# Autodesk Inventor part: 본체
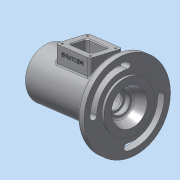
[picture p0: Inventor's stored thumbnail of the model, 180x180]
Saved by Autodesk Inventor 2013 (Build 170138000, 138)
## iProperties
Created: 2017-05
Part Number: 본체
Material: 알루미늄 6061
Document SubType Name: Modeling
Designer: dgall
Density: 2.71 g/cm^3
Mass: 681.559 g
Surface Area: 621.113 cm^2
Volume: 251.498 cm^3
Author: dgall
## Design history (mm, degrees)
sketch "스케치1"
  geometry: L1 (-57.5, 0)-(57.5, 0); L2 (44.5, 53)-(54.5, 53); L3 (57.5, 0)-(57.5, 31); L4 (57.5, 31)-(54.5, 31); L5 (54.5, 31)-(54.5, 53); L6 (44.5, 53)-(44.5, 31); L7 (44.5, 31)-(-57.5, 31); L8 (-57.5, 0)-(-57.5, 31); L9 (43.5, 16)-(57.5, 22); L10 (43.5, 16)-(43.5, 12.5); L11 (43.5, 12.5)-(36.5, 12.5); L12 (36.2, 12.2)-(36.2, 10); L13 (36.2, 10)-(33.5, 10); L14 (33.5, 16.5)-(28.5, 16.5); L15 (33.5, 16.5)-(33.5, 10); L16 (17.5, 26)-(-20.5, 26); L17 (17.5, 26)-(17.5, 17.5); L18 (-20.5, 17.5)-(-31.5, 17.5); L19 (-31.5, 18.5)-(-33.25, 18.5); L20 (-33.25, 17.5)-(-36.5, 17.5); L21 (-20.5, 26)-(-20.5, 17.5); L22 (-31.5, 18.5)-(-31.5, 17.5); L23 (-33.25, 18.5)-(-33.25, 17.5); L24 (-36.5, 20)-(-45.5, 20); L25 (-36.5, 20)-(-36.5, 17.5); L26 (28.5, 17.5)-(17.5, 17.5); L27 (28.5, 17.5)-(28.5, 16.5); L28 (-45.5, 24)-(-48.5, 24); L29 (-45.5, 24)-(-45.5, 20); L30 (-48.5, 24)-(-48.5, 0); A1 r 0.3 centre (36.5, 12.2) between (36.5, 12.5) and (36.2, 12.2); 3 further points
  constraints: 60 end point, 20 perpendicular, 8 parallel, 4 point on line, 2 collinear, 2 point on circle, 2 tangent, 1 centre point, 1 coincident, 1 horizontal, 1 midpoint
  dimensions: "d0" = 115 distance of L1.start L1.end; "d1" = 106 diameter of L2 L1; "d2" = 3 distance of L3.end L4.end; "d3" = 62 diameter of L4 L1; "d4" = 13 distance between parallel lines of L3 L6; "d5" = 14 distance between parallel lines of L3 L10; "d6" = 32 diameter of L9.start L1; "d7" = 44 diameter of L9.end L1; "d8" = 7.3 distance of L10.end point (36.2, 12.5); "d9" = 25 diameter of L11 L1; "d10" = 2.7 distance of L13.end L12.end; "d11" = 20 diameter of L13 L1; "d12" = 0.3 radius of A1; "d13" = 5 distance of L14.end L14.start; "d14" = 33 diameter of L14 L1; "d15" = 38 distance of L16.start L16.end; "d16" = 52 diameter of L16 L1; "d17" = 11 distance of L18.start L18.end; "d18" = 35 diameter of L18 L1; "d19" = 1.75 distance of L19.start L19.end; "d20" = 37 diameter of L19 L1; "d21" = 3.25 distance of L20.start L20.end; "d22" = 9 distance of L24.start L24.end; "d23" = 40 diameter of L24 L1; "d24" = 11 distance of L17.end L26.start; "d25" = 35 diameter of L26 L1; "d26" = 3 distance of L28.start L28.end; "d27" = 48 diameter of L28 L1
revolve "회전1" sketch "스케치1" stored, may be unused: angle "d28" = 90 deg
node "작업 평면1"
sketch "스케치4"
  geometry: L1 (-76.893, 0)-(76.893, 0) reference; L2 (0, -76.893)-(0, 76.893) reference; C1 r 53 at (0, 0) reference; A1 r 4 centre (41.5, 0) between (45.5, 0) and (37.5, 0); A2 r 4 centre (0, -41.5) between (0, -37.5) and (0, -45.5); A3 r 4 centre (0, 41.5) between (0, 37.5) and (0, 45.5); A4 r 4 centre (-41.5, 0) between (-45.5, 0) and (-37.5, 0); A5 r 45.5 centre (0, 0) between (0, 45.5) and (-45.5, 0); A6 r 45.5 centre (0, 0) between (0, -45.5) and (45.5, 0); A7 r 41.5 centre (0, 0) between (3.995, 41.307) and (-41.307, -3.995); A8 r 41.5 centre (0, 0) between (-3.995, -41.307) and (41.307, 3.995); A9 r 37.5 centre (0, 0) between (0, 37.5) and (-37.5, 0); A10 r 37.5 centre (0, 0) between (0, -37.5) and (37.5, 0)
  constraints: 28 point on circle, 10 centre point, 5 equal radius, 5 point on line, 1 coincident
  dimensions: "d43" = 8 diameter of A1; "d46" = 45.5 radius of A6; "d47" = 41.5 radius of A8; "d48" = 37.5 radius of A10
extrude "돌출3" cut sketch "스케치4" stored distance "d49" = 10; taper "d50" = 0 deg
sketch "스케치5"
  geometry: L1 (26.5, -20)-(-23.5, -20); L2 (-23.5, -20)-(-23.5, 20); L3 (-23.5, 20)-(26.5, 20); L4 (26.5, 20)-(26.5, -20); L5 (57.5, 31)-(57.5, -31) reference; L6 (-80.5, 0)-(80.5, 0) reference; 1 further point
  constraints: 8 end point, 2 parallel, 1 horizontal, 1 perpendicular, 1 other
  dimensions: "d56" = 31 distance between parallel lines of L5 L4; "d57" = 50 distance between parallel lines of L2 L4; "d58" = 40 distance between parallel lines of L3 L1
extrude "돌출4" join sketch "스케치5" stored distance "d59" = 10; taper "d60" = 0 deg
sketch "스케치6"
  geometry: L1 (-26.5, -20)-(-26.5, 20) reference; L2 (-17.5, 11)-(14.5, 11); L3 (14.5, 11)-(14.5, -11); L4 (14.5, -11)-(-17.5, -11); L5 (-17.5, -11)-(-17.5, 11); L6 (80.5, 0)-(-80.5, 0) reference; 1 further point
  constraints: 8 end point, 2 parallel, 1 horizontal, 1 perpendicular, 1 other
  dimensions: "d61" = 32 distance between parallel lines of L3 L5; "d63" = 22 distance between parallel lines of L4 L2; "d64" = 9 distance between parallel lines of L1 L5
extrude "돌출5" cut sketch "스케치6" stored distance "d65" = 10; taper "d66" = 0 deg
fillet "모깎기2" dims "d52" = 3
chamfer "모따기1" distance "d53" = 0.7; stored, may be unused: second distance "d54" = 2, angle "d55" = 30 deg
fillet "모깎기3" dims "d67" = 3
hole "구멍1" diameter "d70" = 40.376; stored, may be unused: countersink angle "d74" = 90 deg, drill point angle "d76" = 0 deg; dims "d68" = 10, "d69" = 10, "d71" = 6, "d72" = 4, "d73" = 2, "d75" = 9
fillet "모깎기4" dims "d77" = 3
chamfer "모따기2" distance "d78" = 1; stored, may be unused: second distance "d79" = 2, angle "d80" = 30 deg
fillet "모깎기5" dims "d81" = 0.3
sketch "스케치7"
  geometry: L1 (20.5, -20)-(-23.5, -20) reference; L2 (-26.5, -17)-(-26.5, 17) reference; 2 further points
  dimensions: "d82" = 4.5 distance from line of L2 point (-22, -15.5); "d83" = 4.5 distance from line of L1 point (-22, -15.5)
hole "구멍2" sketch "스케치7" at (-22, -15.5) diameter "d84" = 2.459; stored, may be unused: countersink angle "d88" = 90 deg, drill point angle "d90" = 118 deg; dims "d85" = 6, "d86" = 4, "d87" = 2, "d89" = 8
sketch "스케치8"
  geometry: L1 (44, 0)-(0, 0) reference; L2 (-34, -75)-(-34, -13) reference; 2 further points
  constraints: 1 other
  dimensions: "d97" = 56 distance from line of L2 point (22, -8); "d98" = 8 distance from line of L1 point (22, -8)
feature "엠보싱1" sketch "스케치8" dims "d99" = 0.5, "d100" = 0
node "솔리드1"
pattern_linear "직사각형 패턴1" dims "d93" = 41
pattern_linear "직사각형 패턴2" dims "d96" = 31
other parameters: "d29" = 44, "d40" = 83, "d41" = 75, "d42" = 91
